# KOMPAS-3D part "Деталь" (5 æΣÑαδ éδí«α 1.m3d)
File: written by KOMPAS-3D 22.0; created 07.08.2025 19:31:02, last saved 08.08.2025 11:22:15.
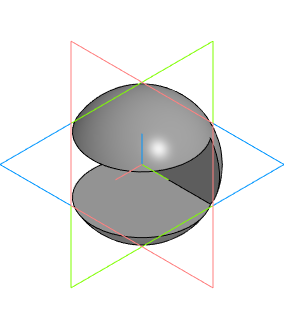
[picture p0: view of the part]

Document properties: Автор: user; Полное имя файла: G:\08 08 пятница\2025 НГ Лаб работы\Лаб 5 Сечения сферы и тора\5 Модели\Сферы Выбор 1.m3d

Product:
- Part/product: Деталь
    Масса: 0.115508

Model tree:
1. Эскиз:1
2. Элемент вращения:1
     Угол 1 = 360
3. Эскиз:2
4. Элемент выдавливания:1
     Расстояние 1 = 20; Расстояние 2 = 20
